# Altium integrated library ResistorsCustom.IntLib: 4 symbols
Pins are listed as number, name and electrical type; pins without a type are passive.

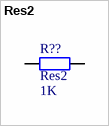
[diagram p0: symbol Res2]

## Res2
designator R??  value 1K
Resistor
footprint Resistor 5W
pins: 1, 2


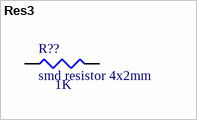
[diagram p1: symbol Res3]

## Res3
designator R??, comment smd resistor 4x2mm  value 1K
footprint smd resistor 4x2mm
pins: 1, 2


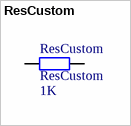
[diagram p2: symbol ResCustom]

## ResCustom
designator ResCustom  value 1K
footprint PCBComponent_1
pins: 1, 2


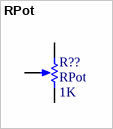
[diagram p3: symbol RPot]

## RPot
designator R??  value 1K
Potentiometer; Sim Note: Enter the Resistance value and the set point into parameter fields.; Set Position: 0.5
footprint potentiometer (Piher)
pins: 1 TOP, 2 BOT, 3 TAP
1 alternate drawing of the same symbol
